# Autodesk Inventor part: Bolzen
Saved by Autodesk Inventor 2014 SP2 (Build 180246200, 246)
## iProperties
Created: 2015-07
Part Number: Bolzen
Material: Generisch
Document SubType Name: Modeling
Designer: e_krauts
Density: 1 g/cm^3
Appearance: Vorgabe
Author: e_krauts
Sending System: SolidWorks 2011
Last Author: e_boekem
Erstellt durch: XYZ
Werkstoff: AlCu4PbMg
Einheit: Stck.
UNIT_OF_MEASURE: Sachnummer
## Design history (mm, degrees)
node "Bolzen.ipt1"
node "Stirnsenkung für M8 Zylinderschraube mit Innensechskant1"
node "Basis1"
